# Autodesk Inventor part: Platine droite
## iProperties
Author: Flavien MARTY
Shininess: 20.0
PropertySet Name: _Private Model Information
Created: 2001-10
Part Number: Platine droite
Material: Par défaut
Document SubType Name: Modélisation
Designer: Flavien MARTY
Control State: 0
Master: False
Checked Out: False
PropertySet Name: Design Tracking Control
Density: 0.0
Volumn: 0.0
Area: 0.0
PropertySet Name: Model Information
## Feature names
1. Base1
